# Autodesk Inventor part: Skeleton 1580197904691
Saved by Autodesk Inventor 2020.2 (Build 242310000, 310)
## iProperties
Created: 2020-01
Part Number: Skeleton 1580197904691
Material: Generic
Document SubType Name: Modeling
Designer: thira
Density: 1 g/cm^3
Appearance: Default
_SkeletonDoc: Frame Skeleton File
_Version: 15.0.0
Author: thira
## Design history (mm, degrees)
sketch "Reference Skeleton"
